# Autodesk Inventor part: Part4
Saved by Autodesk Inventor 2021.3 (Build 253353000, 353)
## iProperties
Created: 2023-09
Part Number: Part4
Material: Generic
Document SubType Name: Modeling
Designer: AdminForWorker
Density: 1 g/cm^3
Appearance: Default
Author: AdminForWorker
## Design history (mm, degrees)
feature "electric_bay"
feature "bottom_plate"
feature "magnet_distance_10mm"
feature "magnetholder_12x12x12"
feature "top_plate"
body "Solid1"
body "Solid2"
body "Solid3"
body "Solid4"
body "Solid5"
